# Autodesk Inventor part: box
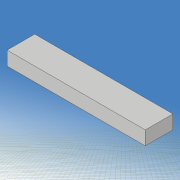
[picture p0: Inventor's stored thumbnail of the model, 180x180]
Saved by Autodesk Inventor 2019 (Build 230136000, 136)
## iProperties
Created: 2021-05
Part Number: box
Material: 一般
Document SubType Name: Modeling
Designer: kikut
Density: 1 g/cm^3
Appearance: 既定
Author: kikut
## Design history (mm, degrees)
sketch "スケッチ1"
  geometry: L1 (-100, -10)-(100, -10); L2 (100, -10)-(100, 10); L3 (100, 10)-(-100, 10); L4 (-100, 10)-(-100, -10); L5 (-100, -10)-(100, 10); L6 (100, -10)-(-100, 10); 1 further point
  constraints: 12 end point, 2 midpoint, 2 parallel, 1 horizontal, 1 perpendicular
  dimensions: "d0" = 200 distance of L2.end L3.end; "d1" = 20 distance of L1.end L2.end
extrude "押し出し1" new body sketch "スケッチ1" stored distance "d2" = 40; taper "d3" = 0 deg
node "ソリッド1"
